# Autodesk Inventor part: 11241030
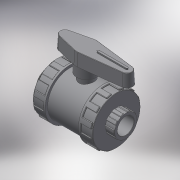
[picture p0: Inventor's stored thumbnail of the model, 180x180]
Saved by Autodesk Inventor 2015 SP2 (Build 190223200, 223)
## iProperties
Created: 2017-11
Part Number: 11241030
Material: Generic
Description: PLASSON BI STOP VALVE THR PVC 3"
Document SubType Name: Modeling
Designer: KIM
Density: 1 g/cm^3
Appearance: Default
Author: KIM
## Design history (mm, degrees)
derived "112410 - 112710.ipt"
feature "Solid1::112410 - 112710.ipt"
tag "TaggingFeature1"
body "Solid1"
other parameters: "d1" = 84.926, "d2" = 165, "d3" = 51, "d4" = 67.9408, "d5" = 35.7, "d7" = 118.8964, "d8" = 148.5, "d13" = 2.54778, "d23" = 51, "d24" = 158.4, "d25" = 1.69852, "d26" = 2.54778, "d27" = 24.75, "d28" = 12.375, "d29" = 38.25, "d30" = 0, "d35" = 2.54778, "d39" = 82.5, "d45" = 360 deg, "d47" = 1.69852, "d50" = 90.75, "d51" = 49.5, "d53" = 0, "d55" = 16.9852, "d56" = 8.4926, "d57" = 35.7, "d58" = 0, "d59" = 2.54778, "d61" = 360 deg, "d63" = 66, "d64" = 146, "d66" = 153, "d68" = 33, "d69" = 45.9, "d70" = 36.5, "d71" = 3 deg, "d73" = 3.3, "d74" = 61.2, "d75" = 4.38, "d76" = 0, "d77" = 1.69852, "G_" = 84.926, "l_" = 51, "K_" = 165, "F_" = 146, "J_" = 153, "d67" = 66, "d72" = 16.5
